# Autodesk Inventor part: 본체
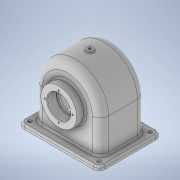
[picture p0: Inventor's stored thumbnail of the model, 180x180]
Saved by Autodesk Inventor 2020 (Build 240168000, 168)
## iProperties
Created: 2022-09
Part Number: 본체
Material: 일반
Document SubType Name: Modeling
Designer: Administrator
Density: 1 g/cm^3
Appearance: 기본값
Author: Administrator
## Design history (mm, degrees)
sketch "스케치1"
  geometry: L1 (-54, 70)-(54, 70); L2 (54, 70)-(54, -70); L3 (54, -70)-(-54, -70); L4 (-54, -70)-(-54, 70); L5 (-54, 70)-(54, -70); L6 (54, 70)-(-54, -70); 1 further point
  constraints: 12 end point, 2 midpoint, 2 parallel, 1 horizontal, 1 perpendicular
  dimensions: "d0" = 140 distance between parallel lines of L3 L1; "d1" = 108 distance between parallel lines of L2 L4
extrude "돌출1" new body sketch "스케치1" distance "d2" = 7; taper "d3" = 0 deg
node "작업 평면3"
sketch "스케치10"
  geometry: L1 (64, 127)-(7, 127); L2 (7, 0)-(7, 140) reference; L3 (64, 13)-(7, 13); L4 (0, 0)-(0, 140) reference; A1 r 57 centre (64, 70) between (64, 13) and (64, 127); 1 further point
  constraints: 4 end point, 2 point on circle, 2 point on line, 2 tangent, 1 centre point, 1 horizontal, 1 horizontal alignment, 1 perpendicular
  dimensions: "d42" = 57 radius of A1; "d43" = 64 distance from line of A1.centre L4
extrude "돌출7" join sketch "스케치10" distance "d44" = 78; taper "d45" = 0 deg
fillet "모깎기4" dims "d46" = 14
node "작업 평면4"
sketch "스케치11"
  geometry: L1 (0, 140)-(0, 0) reference; C1 r 31 at (64, 70); 2 further points
  constraints: 1 centre point, 1 horizontal alignment, 1 midpoint
  dimensions: "d48" = 31 radius of C1; "d49" = 64 distance from line of C1.centre L1
feature "쉘3" dims "d50" = 5
extrude "돌출8" join sketch "스케치11" stored distance "d51" = 78; taper "d52" = 0 deg
sketch "스케치13"
  geometry: L1 (-39, 64)-(-39, 107) reference; L2 (-39, 64)-(71.768, 64); L3 (54, 33)-(54, 95) reference; L4 (54, 84)-(38, 84); L5 (38, 84)-(38, 81.5); L6 (38, 81.5)-(33, 81.5); L7 (39, 107)-(39, 64) reference; L8 (33, 81.5)-(33, 64); L9 (25, 64)-(39, 64) reference; 3 further points
  constraints: 10 end point, 3 perpendicular, 2 horizontal, 2 point on line
  dimensions: "d53" = 40 diameter of L4 L2; "d54" = 35 diameter of L6 L2; "d55" = 16 distance from line of L4.end L3; "d56" = 5 distance from line of L5.end L8
revolve "회전3" sketch "스케치13" stored, may be unused: angle "d57" = 90 deg
sketch "스케치15"
  geometry: C1 r 32 at (-64, 70); A1 r 43 centre (-64, 70) between (-64, 113) and (-64, 27) reference; 1 further point
  constraints: 1 centre point, 1 coincident
  dimensions: "d64" = 32 radius of C1
extrude "돌출10" cut sketch "스케치15" distance "d65" = 5; taper "d66" = 0 deg
node "작업 평면6"
sketch "스케치17"
  geometry: C1 r 28 at (0, 0); 1 further point
  constraints: 1 centre point
  dimensions: "d72" = 28 radius of C1
extrude "돌출12" join sketch "스케치17" stored distance "d73" = 14; taper "d74" = 30 deg
sketch "스케치18"
  geometry: C1 r 20 at (0, 0) reference; C2 r 20 at (0, 0); 1 further point
  constraints: 1 centre point, 1 coincident
  dimensions: "d75" = 20 radius of C2
extrude "돌출13" cut sketch "스케치18" distance "d76" = 16; taper "d77" = 0 deg
sketch "스케치19" dims "d78" = 24
  geometry: C1 r 20 at (0, 0) reference; C2 r 28 at (0, 0) reference; 3 further points
  constraints: 2 horizontal alignment, 1 coincident, 2 other
hole "구멍1" sketch "스케치19" at (24, 0) diameter "d79" = 2.459; stored, may be unused: countersink angle "d83" = 90 deg, drill point angle "d85" = 118 deg; dims "d80" = 7, "d81" = 8, "d82" = 4.4, "d84" = 9
sketch "스케치20" dims "d89" = 24
  geometry: C1 r 20 at (0, 0) reference; C2 r 32 at (0, 0) reference; 3 further points
  constraints: 2 horizontal alignment, 1 coincident, 2 other
hole "구멍2" sketch "스케치20" at (-24, 0) diameter "d90" = 2.459; stored, may be unused: countersink angle "d94" = 90 deg, drill point angle "d96" = 118 deg; dims "d91" = 7, "d92" = 8, "d93" = 4.4, "d95" = 9
node "작업 평면7"
sketch "스케치21"
  geometry: C1 r 6 at (49, 65); 1 further point
  constraints: 1 centre point, 1 coincident
  dimensions: "d101" = 6 radius of C1
extrude "돌출14" join sketch "스케치21" stored distance "d102" = 16; taper "d103" = 0 deg
fillet "모깎기5" dims "d104" = 1
sketch "스케치22"
  geometry: C1 r 6 at (0, 0) reference; 2 further points
  constraints: 1 coincident
hole "구멍3" sketch "스케치22" at (0, 0) diameter "d105" = 5.1881; stored, may be unused: countersink angle "d109" = 90 deg, drill point angle "d111" = 118 deg; dims "d106" = 12, "d107" = 8, "d108" = 4.4, "d110" = 15
chamfer "모따기1" distance "d112" = 1; stored, may be unused: second distance "d113" = 2, angle "d114" = 45 deg
chamfer "모따기2" distance "d115" = 1; stored, may be unused: second distance "d116" = 2, angle "d117" = 45 deg
fillet "모깎기6" dims "d118" = 10, "d119" = 3
sketch "스케치23"
  geometry: L1 (64, 0)-(64, 54) reference; L2 (69, 64)-(-19, 64) reference; 2 further points
  constraints: 1 other
  dimensions: "d120" = 39 distance from line of point (25, 47) L1; "d121" = 17 distance from line of point (25, 47) L2
feature "엠보싱1" sketch "스케치23" dims "d122" = 0.5, "d123" = 0
fillet "모깎기7" dims "d124" = 3
fillet "모깎기8" dims "d125" = 3
sketch "스케치26"
  geometry: L1 (49, 65)-(49, -65) reference; L2 (49, -65)-(-49, -65) reference; L3 (-49, -65)-(-49, 65) reference; L4 (-49, 65)-(49, 65) reference; L5 (-49, 65)-(49, 65) reference; L6 (49, -65)-(-49, -65); L7 (-49, -65)-(-49, 65); L8 (-49, 65)-(49, 65); L9 (49, 65)-(49, -65); L10 (49, -65)-(-49, 65); L11 (-49, -65)-(49, 65); L12 (25, 52)-(-25, 52); L13 (-34, 43)-(-34, -43); L14 (-25, -52)-(25, -52); L15 (34, -43)-(34, 43); L16 (34, 52)-(-34, -52); L17 (-34, 52)-(34, -52); L18 (-34, 43)-(-34, -43) reference; L19 (34, -43)-(34, 43) reference; L20 (25, 52)-(-25, 52) reference; L21 (-25, -52)-(25, -52) reference; C1 r 2.594 at (0, 0) reference; A1 r 9 centre (-25, 43) between (-25, 52) and (-34, 43); A2 r 9 centre (25, 43) between (34, 43) and (25, 52); A3 r 9 centre (25, -43) between (25, -52) and (34, -43); A4 r 9 centre (-25, -43) between (-34, -43) and (-25, -52); 1 further point
  constraints: 24 end point, 9 point on line, 8 point on circle, 8 tangent, 4 centre point, 4 midpoint, 4 parallel, 2 horizontal, 2 perpendicular, 1 equal radius
  dimensions: "d135" = 9 radius of A1; "d136" = 9 radius of A2; "d137" = 9 radius of A4 (derived); "d138" = 104 distance between parallel lines of L12 L21
extrude "돌출16" join sketch "스케치26" distance "d139" = 2; taper "d140" = 0 deg
sketch "스케치24"
  geometry: A1 r 7 centre (44, 60) between (51, 60) and (44, 67) reference; A2 r 7 centre (-44, 60) between (-44, 67) and (-51, 60) reference; A3 r 7 centre (-44, -60) between (-51, -60) and (-44, -67) reference; A4 r 7 centre (44, -60) between (44, -67) and (51, -60) reference; 5 further points
  constraints: 4 coincident
hole "구멍4" sketch "스케치24" at (-44, 60), (44, -60), (-44, -60), (44, 60) diameter "d126" = 6.6; stored, may be unused: countersink angle "d130" = 90 deg, drill point angle "d132" = 0 deg; dims "d127" = 12, "d128" = 8, "d129" = 4.4, "d131" = 16
fillet "모깎기9" dims "d141" = 0.6
node "솔리드1"
pattern_circular "원형 패턴1" dims angle "d87" = 360 deg
pattern_circular "원형 패턴2" dims angle "d98" = 360 deg
feature "A9D066F2-1C7D-4E18-AEED-F7BC21143FA4" dims "d126" = 6.6, "d127" = 12, "d128" = 8, "d129" = 4.4, "d130" = 90 deg, "d131" = 16, "d132" = 0
other parameters: "d40" = -15, "d47" = 15, "d71" = 16, "d100" = -122
